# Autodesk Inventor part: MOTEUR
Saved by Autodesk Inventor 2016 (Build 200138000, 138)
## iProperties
Created: 2013-10
Part Number: MOTEUR
Material: Générique
Document SubType Name: Modeling
Designer: Bruno
Density: 1 g/cm^3
Appearance: Par défaut
Author: Bruno
Sending System: SolidWorks 2013
Last Author: christophe
Last Saved: 2014-02-15
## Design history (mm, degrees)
feature "Enlèv. mat.-Extru.3"
node "Solide1"
